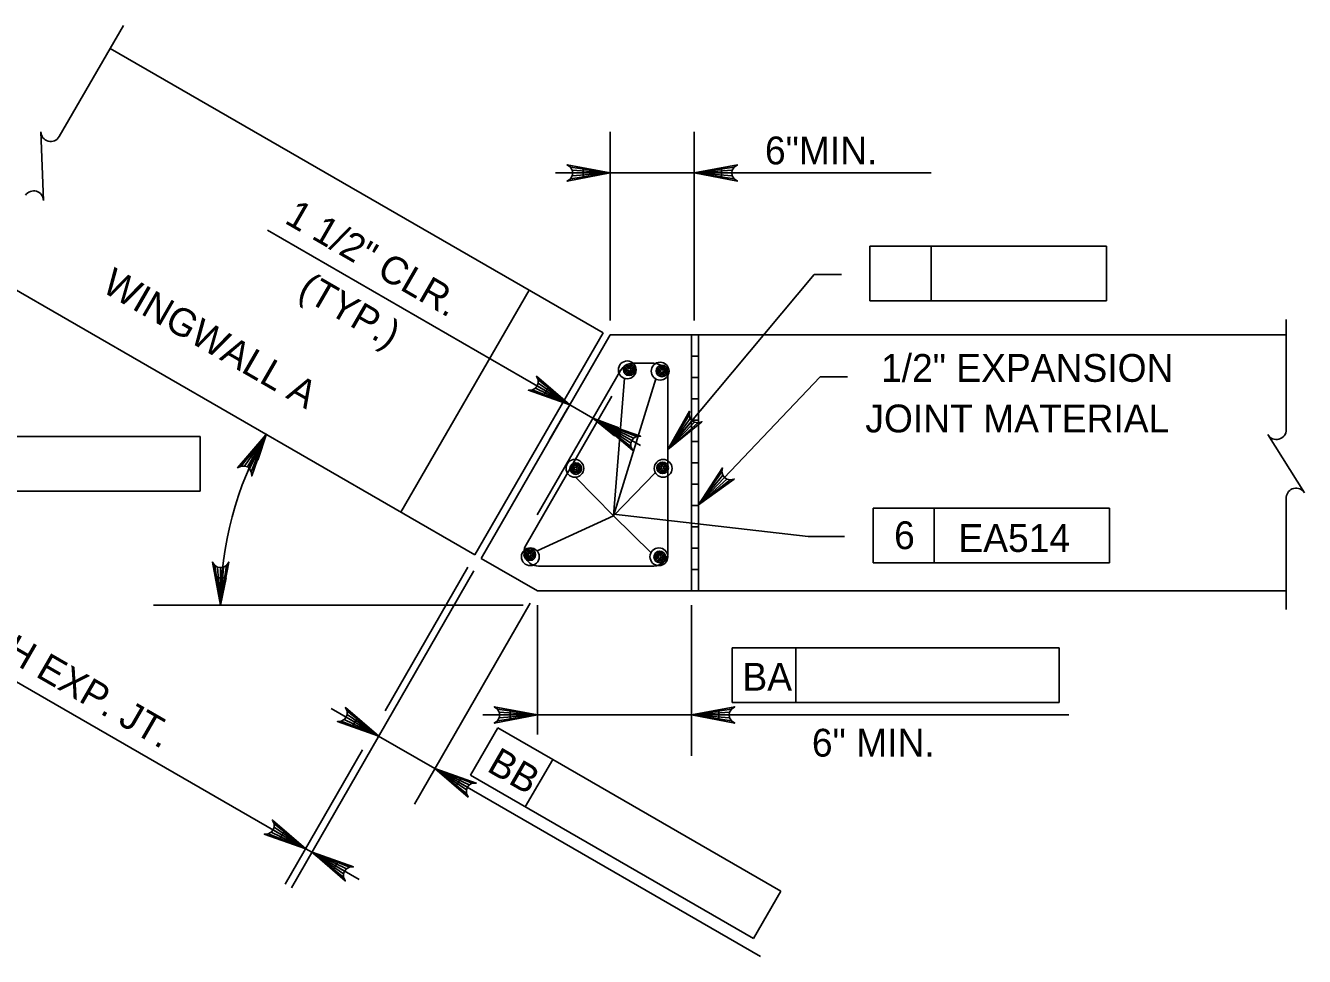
# Model space of a CAD drawing. Extents: x 638340 to 640242, y 295465 to 298435.
# Drawn here: x 638577.5 to 638715.4, y 297538.8 to 297639.2 of the extents above; entities that cross this region are included whole.
import ezdxf

# ---------------------------------------------------------------- set-up
doc = ezdxf.new("R2010")
doc.units = 0
for name, color, linetype in [('Level 10', 7, 'Continuous'), ('Level 3', 7, 'Continuous'), ('Level 4', 7, 'Continuous'), ('Level 5', 7, 'Continuous')]:
    doc.layers.add(name, color=color, linetype=linetype)

msp = doc.modelspace()

# ---------------------------------------------------------------- linework, layer by layer
at = {"layer": 'Level 10'}
for p, q in [((638639.77, 297606.06), (638586.65, 297636.73)), ((638625.96, 297582.13), (638572.83, 297612.8)), ((638631.8, 297610.66), (638617.98, 297586.74)), ((638639.77, 297606.06), (638625.96, 297582.13)), ((638640.55, 297605.87), (638626.62, 297581.75)), ((638713.41, 297605.87), (638640.55, 297605.87)), ((638649.31, 297605.87), (638649.31, 297578.24)), ((638650.07, 297605.87), (638650.07, 297578.24)), ((638632.69, 297578.24), (638626.62, 297581.75)), ((638713.41, 297578.24), (638632.69, 297578.24))]:
    msp.add_line(p, q, dxfattribs=at)
at = {"layer": 'Level 3'}
for p, q in [((638640.55, 297607.41), (638640.55, 297627.73)), ((638649.59, 297607.41), (638649.59, 297627.73)), ((638640.55, 297623.31), (638634.66, 297623.31)), ((638649.59, 297623.31), (638640.55, 297623.31)), ((638649.59, 297623.31), (638675.15, 297623.31)), ((638631.09, 297601.26), (638603.6, 297617.13)), ((638668.54, 297615.43), (638694.03, 297615.43)), ((638668.54, 297609.53), (638668.54, 297615.43)), ((638675.12, 297609.53), (638675.12, 297615.43)), ((638694.03, 297615.43), (638694.03, 297609.53)), ((638646.77, 297593.48), (638662.52, 297612.37)), ((638662.52, 297612.37), (638665.47, 297612.37)), ((638694.03, 297609.53), (638668.54, 297609.53)), ((638636.19, 297598.32), (638631.09, 297601.26)), ((638650.07, 297587.54), (638663.18, 297601.33)), ((638663.18, 297601.33), (638666.13, 297601.33)), ((638635.95, 297597.9), (638633.98, 297594.49)), ((638567.95, 297594.89), (638596.35, 297594.89)), ((638596.35, 297589), (638596.35, 297594.89)), ((638596.35, 297589), (638561.12, 297589)), ((638668.88, 297587.16), (638694.37, 297587.16)), ((638668.88, 297581.27), (638668.88, 297587.16)), ((638675.46, 297581.27), (638675.46, 297587.16)), ((638694.37, 297587.16), (638694.37, 297581.27)), ((638661.87, 297584.11), (638665.81, 297584.11)), ((638625.19, 297580.8), (638616.28, 297565.32)), ((638694.37, 297581.27), (638668.88, 297581.27)), ((638602.62, 297553.39), (638555.97, 297580.33)), ((638625.86, 297580.42), (638606.18, 297546.24)), ((638631.16, 297576.71), (638591.33, 297576.71)), ((638631.92, 297576.92), (638619.43, 297555.27)), ((638632.69, 297576.71), (638632.69, 297562.75)), ((638649.31, 297576.71), (638649.31, 297560.45)), ((638653.7, 297566.21), (638653.7, 297572.1)), ((638653.7, 297572.1), (638660.54, 297572.1)), ((638660.54, 297566.21), (638660.54, 297572.1)), ((638660.54, 297572.1), (638688.94, 297572.1)), ((638688.94, 297572.1), (638688.94, 297566.21)), ((638613.02, 297564.08), (638610.47, 297565.55)), ((638688.94, 297566.21), (638653.7, 297566.21)), ((638629.75, 297564.87), (638626.8, 297564.87)), ((638632.69, 297564.87), (638657, 297564.87)), ((638652.25, 297564.87), (638655.2, 297564.87)), ((638655.2, 297564.87), (638689.99, 297564.87)), ((638625.47, 297558.38), (638628.42, 297563.49)), ((638628.42, 297563.49), (638634.34, 297560.07)), ((638615.57, 297562.6), (638621.64, 297559.1)), ((638613.86, 297561.11), (638605.51, 297546.62)), ((638631.39, 297554.97), (638634.34, 297560.07)), ((638634.34, 297560.07), (638658.93, 297545.87)), ((638624.19, 297557.63), (638626.74, 297556.15)), ((638655.99, 297540.77), (638625.47, 297558.38)), ((638626.74, 297556.15), (638656.74, 297538.83)), ((638605.17, 297551.92), (638602.62, 297553.39)), ((638608.39, 297550.06), (638607.72, 297550.45)), ((638610.94, 297548.59), (638613.49, 297547.12)), ((638658.93, 297545.87), (638655.99, 297540.77))]:
    msp.add_line(p, q, dxfattribs=at)
for points in [[(638640.55, 297623.31), (638635.9, 297622.44), (638636.26, 297622.69), (638636.45, 297623), (638636.5, 297623.31), (638636.45, 297623.62), (638636.26, 297623.94), (638635.9, 297624.18), (638640.55, 297623.31), (638636.26, 297623.94), (638636.45, 297623.62), (638640.55, 297623.31), (638636.5, 297623.31), (638636.45, 297623), (638640.55, 297623.31), (638636.26, 297622.69)], [(638649.59, 297623.31), (638654.25, 297624.18), (638653.89, 297623.94), (638653.7, 297623.62), (638653.65, 297623.31), (638653.7, 297623), (638653.89, 297622.69), (638654.25, 297622.44), (638649.59, 297623.31), (638653.89, 297622.69), (638653.7, 297623), (638649.59, 297623.31), (638653.65, 297623.31), (638653.7, 297623.62), (638649.59, 297623.31), (638653.89, 297623.94)], [(638636.19, 297598.32), (638631.72, 297599.89), (638632.16, 297599.93), (638632.48, 297600.1), (638632.68, 297600.35), (638632.79, 297600.64), (638632.79, 297601.01), (638632.6, 297601.4), (638636.19, 297598.32), (638632.79, 297601.01), (638632.79, 297600.64), (638636.19, 297598.32), (638632.68, 297600.35), (638632.48, 297600.1), (638636.19, 297598.32), (638632.16, 297599.93)], [(638646.77, 297593.48), (638649.08, 297597.61), (638649.04, 297597.18), (638649.16, 297596.84), (638649.37, 297596.6), (638649.64, 297596.44), (638650, 297596.38), (638650.42, 297596.49), (638646.77, 297593.48), (638650, 297596.38), (638649.64, 297596.44), (638646.77, 297593.48), (638649.37, 297596.6), (638649.16, 297596.84), (638646.77, 297593.48), (638649.04, 297597.18)], [(638603.46, 297595.12), (638601.9, 297590.65), (638601.86, 297591.09), (638601.68, 297591.4), (638601.44, 297591.61), (638601.14, 297591.71), (638600.78, 297591.71), (638600.38, 297591.52), (638603.46, 297595.12), (638600.78, 297591.71), (638601.14, 297591.71), (638603.46, 297595.12), (638601.44, 297591.61), (638601.68, 297591.4), (638603.46, 297595.12), (638601.86, 297591.09)], [(638650.07, 297587.54), (638652.65, 297591.51), (638652.58, 297591.08), (638652.68, 297590.73), (638652.87, 297590.48), (638653.13, 297590.3), (638653.48, 297590.22), (638653.91, 297590.31), (638650.07, 297587.54), (638653.48, 297590.22), (638653.13, 297590.3), (638650.07, 297587.54), (638652.87, 297590.48), (638652.68, 297590.73), (638650.07, 297587.54), (638652.58, 297591.08)], [(638598.54, 297576.71), (638597.67, 297581.36), (638597.92, 297581), (638598.23, 297580.82), (638598.54, 297580.76), (638598.86, 297580.82), (638599.17, 297581), (638599.42, 297581.36), (638598.54, 297576.71), (638599.17, 297581), (638598.86, 297580.82), (638598.54, 297576.71), (638598.54, 297580.76), (638598.23, 297580.82), (638598.54, 297576.71), (638597.92, 297581)], [(638615.59, 297562.59), (638611.13, 297564.16), (638611.56, 297564.2), (638611.88, 297564.38), (638612.08, 297564.62), (638612.19, 297564.92), (638612.19, 297565.28), (638612, 297565.67), (638615.59, 297562.59), (638612.19, 297565.28), (638612.19, 297564.92), (638615.59, 297562.59), (638612.08, 297564.62), (638611.88, 297564.38), (638615.59, 297562.59), (638611.56, 297564.2)], [(638632.69, 297564.87), (638628.04, 297564), (638628.4, 297564.25), (638628.58, 297564.56), (638628.64, 297564.87), (638628.58, 297565.19), (638628.4, 297565.5), (638628.04, 297565.75), (638632.69, 297564.87), (638628.4, 297565.5), (638628.58, 297565.19), (638632.69, 297564.87), (638628.64, 297564.87), (638628.58, 297564.56), (638632.69, 297564.87), (638628.4, 297564.25)], [(638649.31, 297564.87), (638653.96, 297565.75), (638653.6, 297565.5), (638653.41, 297565.19), (638653.36, 297564.87), (638653.41, 297564.56), (638653.6, 297564.25), (638653.96, 297564), (638649.31, 297564.87), (638653.6, 297564.25), (638653.41, 297564.56), (638649.31, 297564.87), (638653.36, 297564.87), (638653.41, 297565.19), (638649.31, 297564.87), (638653.6, 297565.5)], [(638621.64, 297559.1), (638626.1, 297557.53), (638625.67, 297557.5), (638625.35, 297557.32), (638625.15, 297557.07), (638625.04, 297556.78), (638625.05, 297556.42), (638625.23, 297556.02), (638621.64, 297559.1), (638625.05, 297556.42), (638625.04, 297556.78), (638621.64, 297559.1), (638625.15, 297557.07), (638625.35, 297557.32), (638621.64, 297559.1), (638625.67, 297557.5)], [(638607.72, 297550.45), (638603.25, 297552.02), (638603.69, 297552.06), (638604, 297552.24), (638604.21, 297552.48), (638604.31, 297552.78), (638604.31, 297553.14), (638604.13, 297553.53), (638607.72, 297550.45), (638604.31, 297553.14), (638604.31, 297552.78), (638607.72, 297550.45), (638604.21, 297552.48), (638604, 297552.24), (638607.72, 297550.45), (638603.69, 297552.06)], [(638608.4, 297550.06), (638612.86, 297548.49), (638612.43, 297548.45), (638612.11, 297548.28), (638611.91, 297548.03), (638611.8, 297547.74), (638611.8, 297547.37), (638611.99, 297546.98), (638608.4, 297550.06), (638611.8, 297547.37), (638611.8, 297547.74), (638608.4, 297550.06), (638611.91, 297548.03), (638612.11, 297548.28), (638608.4, 297550.06), (638612.43, 297548.45)]]:
    msp.add_lwpolyline(points, dxfattribs=at)
for points in [[(638637.61, 297623.8), (638637.61, 297622.82), (638640.55, 297623.31)], [(638652.54, 297623.8), (638652.54, 297622.82), (638649.59, 297623.31)], [(638633.89, 297600.22), (638633.39, 297599.37), (638636.19, 297598.32)], [(638602.56, 297592.34), (638601.69, 297592.8), (638603.49, 297595.18)], [(638598.17, 297579.67), (638599.15, 297579.64), (638598.54, 297576.71)], [(638613.26, 297564.5), (638612.77, 297563.65), (638615.57, 297562.6)], [(638629.75, 297565.37), (638629.75, 297564.38), (638632.69, 297564.87)], [(638652.25, 297565.37), (638652.25, 297564.38), (638649.31, 297564.87)], [(638624.43, 297558.05), (638623.94, 297557.2), (638621.64, 297559.1)], [(638605.42, 297552.35), (638604.93, 297551.5), (638607.72, 297550.45)], [(638611.18, 297549.02), (638610.69, 297548.17), (638608.39, 297550.06)]]:
    msp.add_lwpolyline(points, close=True, dxfattribs=at)
msp.add_arc((638635.48, 297576.71), 36.94, 150.1038, 180, dxfattribs=at)
at = {"layer": 'Level 4'}
for p, q in [((638588.07, 297639.21), (638581.16, 297627.23)), ((638579.18, 297627.76), (638579.46, 297620.36)), ((638713.41, 297607.52), (638713.41, 297597.01)), ((638713.41, 297597.01), (638713.41, 297595.63)), ((638711.42, 297595.1), (638715.37, 297588.83)), ((638713.41, 297588.36), (638713.41, 297587.13)), ((638713.41, 297588.31), (638713.41, 297576.23))]:
    msp.add_line(p, q, dxfattribs=at)
for centre, start, end in [((638580.24, 297627.76), 180, 330), ((638578.39, 297620.32), 2.1328, 144.6714), ((638712.35, 297595.63), 210, 0), ((638714.47, 297588.26), 32.1328, 174.6714)]:
    msp.add_arc(centre, 1.06, start, end, dxfattribs=at)
at = {"layer": 'Level 5'}
for p, q in [((638649.31, 297605.87), (638650.07, 297605.87)), ((638642.99, 297602.8), (638645.23, 297602.8)), ((638649.31, 297603.57), (638650.07, 297603.57)), ((638641.66, 297602.03), (638632.66, 297586.44)), ((638646.77, 297601.26), (638646.77, 297582.46)), ((638649.31, 297601.27), (638650.07, 297601.27)), ((638642.07, 297601.18), (638640.89, 297586.34)), ((638640.89, 297586.34), (638645.45, 297601.11)), ((638640.72, 297599.26), (638631.47, 297583.23)), ((638649.31, 297598.97), (638650.07, 297598.97)), ((638638.68, 297596.88), (638636.19, 297598.32)), ((638639.35, 297596.49), (638643.79, 297593.93)), ((638649.31, 297596.67), (638650.07, 297596.67)), ((638649.31, 297594.36), (638650.07, 297594.36)), ((638649.31, 297592.06), (638650.07, 297592.06)), ((638636.8, 297590.51), (638640.89, 297586.34)), ((638640.89, 297586.34), (638645.41, 297591)), ((638649.31, 297589.76), (638650.07, 297589.76)), ((638632.66, 297582.56), (638640.89, 297586.34)), ((638640.89, 297586.52), (638661.87, 297584.11)), ((638640.89, 297586.34), (638644.94, 297582.36)), ((638649.3, 297587.45), (638650.07, 297587.45)), ((638649.31, 297585.15), (638650.07, 297585.15)), ((638649.3, 297582.85), (638650.07, 297582.85)), ((638632.8, 297580.92), (638645.23, 297580.92)), ((638649.31, 297580.55), (638650.07, 297580.55)), ((638649.3, 297578.25), (638649.52, 297578.24))]:
    msp.add_line(p, q, dxfattribs=at)
msp.add_lwpolyline([(638641.48, 297595.83), (638640.99, 297594.98), (638638.68, 297596.88)], close=True, dxfattribs=at)
msp.add_lwpolyline([(638639.35, 297596.49), (638643.81, 297594.92), (638643.38, 297594.89), (638643.06, 297594.71), (638642.86, 297594.47), (638642.75, 297594.17), (638642.76, 297593.81), (638642.94, 297593.41), (638639.35, 297596.49), (638642.76, 297593.81), (638642.75, 297594.17), (638639.35, 297596.49), (638642.86, 297594.47), (638643.06, 297594.71), (638639.35, 297596.49), (638643.38, 297594.89)], dxfattribs=at)
for centre, radius in [((638642.38, 297602.08), 0.96), ((638642.59, 297602.1), 0.624), ((638645.92, 297601.94), 0.96), ((638642.59, 297602.1), 0.468), ((638642.59, 297602.1), 0.312), ((638642.59, 297602.1), 0.156), ((638646.12, 297601.96), 0.624), ((638646.12, 297601.96), 0.468), ((638646.12, 297601.96), 0.312), ((638646.12, 297601.96), 0.156), ((638636.74, 297591.46), 0.96), ((638636.83, 297591.44), 0.624), ((638636.83, 297591.44), 0.468), ((638636.83, 297591.44), 0.312), ((638636.83, 297591.44), 0.156), ((638646.25, 297591.46), 0.96), ((638646.19, 297591.52), 0.624), ((638646.19, 297591.52), 0.468), ((638646.19, 297591.52), 0.312), ((638646.19, 297591.52), 0.156), ((638631.93, 297581.93), 0.96), ((638631.87, 297582.15), 0.624), ((638631.87, 297582.15), 0.468), ((638631.87, 297582.15), 0.312), ((638631.87, 297582.15), 0.156), ((638645.79, 297581.93), 0.96), ((638645.88, 297581.91), 0.624), ((638645.88, 297581.91), 0.468), ((638645.88, 297581.91), 0.312), ((638645.88, 297581.91), 0.156)]:
    msp.add_circle(centre, radius, dxfattribs=at)
for centre, start, end in [((638642.99, 297601.26), 90, 150), ((638645.24, 297601.26), 0, 90), ((638632.8, 297582.46), 150, 270), ((638645.24, 297582.46), 270, 0)]:
    msp.add_arc(centre, 1.53, start, end, dxfattribs=at)

# ---------------------------------------------------------------- texts
at = {"layer": 'Level 3'}
for s, height, p in [('6"MIN.', 3, (638657.22, 297624.24)), ('1/2" EXPANSION', 3.0001, (638669.73, 297600.79)), ('JOINT MATERIAL', 3.0001, (638668.04, 297595.34)), ('6', 3, (638671.14, 297582.75)), ('EA514', 3, (638678.07, 297582.45)), ('BA', 3, (638654.79, 297567.49)), ('6" MIN.', 3, (638662.28, 297560.38))]:
    msp.add_text(s, height=height, dxfattribs=at).set_placement(p)
for s, height, p in [('1 1/2" CLR.', 3.0001, (638605.32, 297617.98)), ('WINGWALL A', 3, (638585.59, 297610.61)), ('(TYP.)', 3, (638606.73, 297610.12)), ('1/2" FLUSH EXP. JT.', 3.0001, (638559.11, 297580.27)), ('BB', 3, (638627.12, 297558.89))]:
    msp.add_text(s, height=height, rotation=330, dxfattribs=at).set_placement(p)

doc.saveas('drawing.dxf')
